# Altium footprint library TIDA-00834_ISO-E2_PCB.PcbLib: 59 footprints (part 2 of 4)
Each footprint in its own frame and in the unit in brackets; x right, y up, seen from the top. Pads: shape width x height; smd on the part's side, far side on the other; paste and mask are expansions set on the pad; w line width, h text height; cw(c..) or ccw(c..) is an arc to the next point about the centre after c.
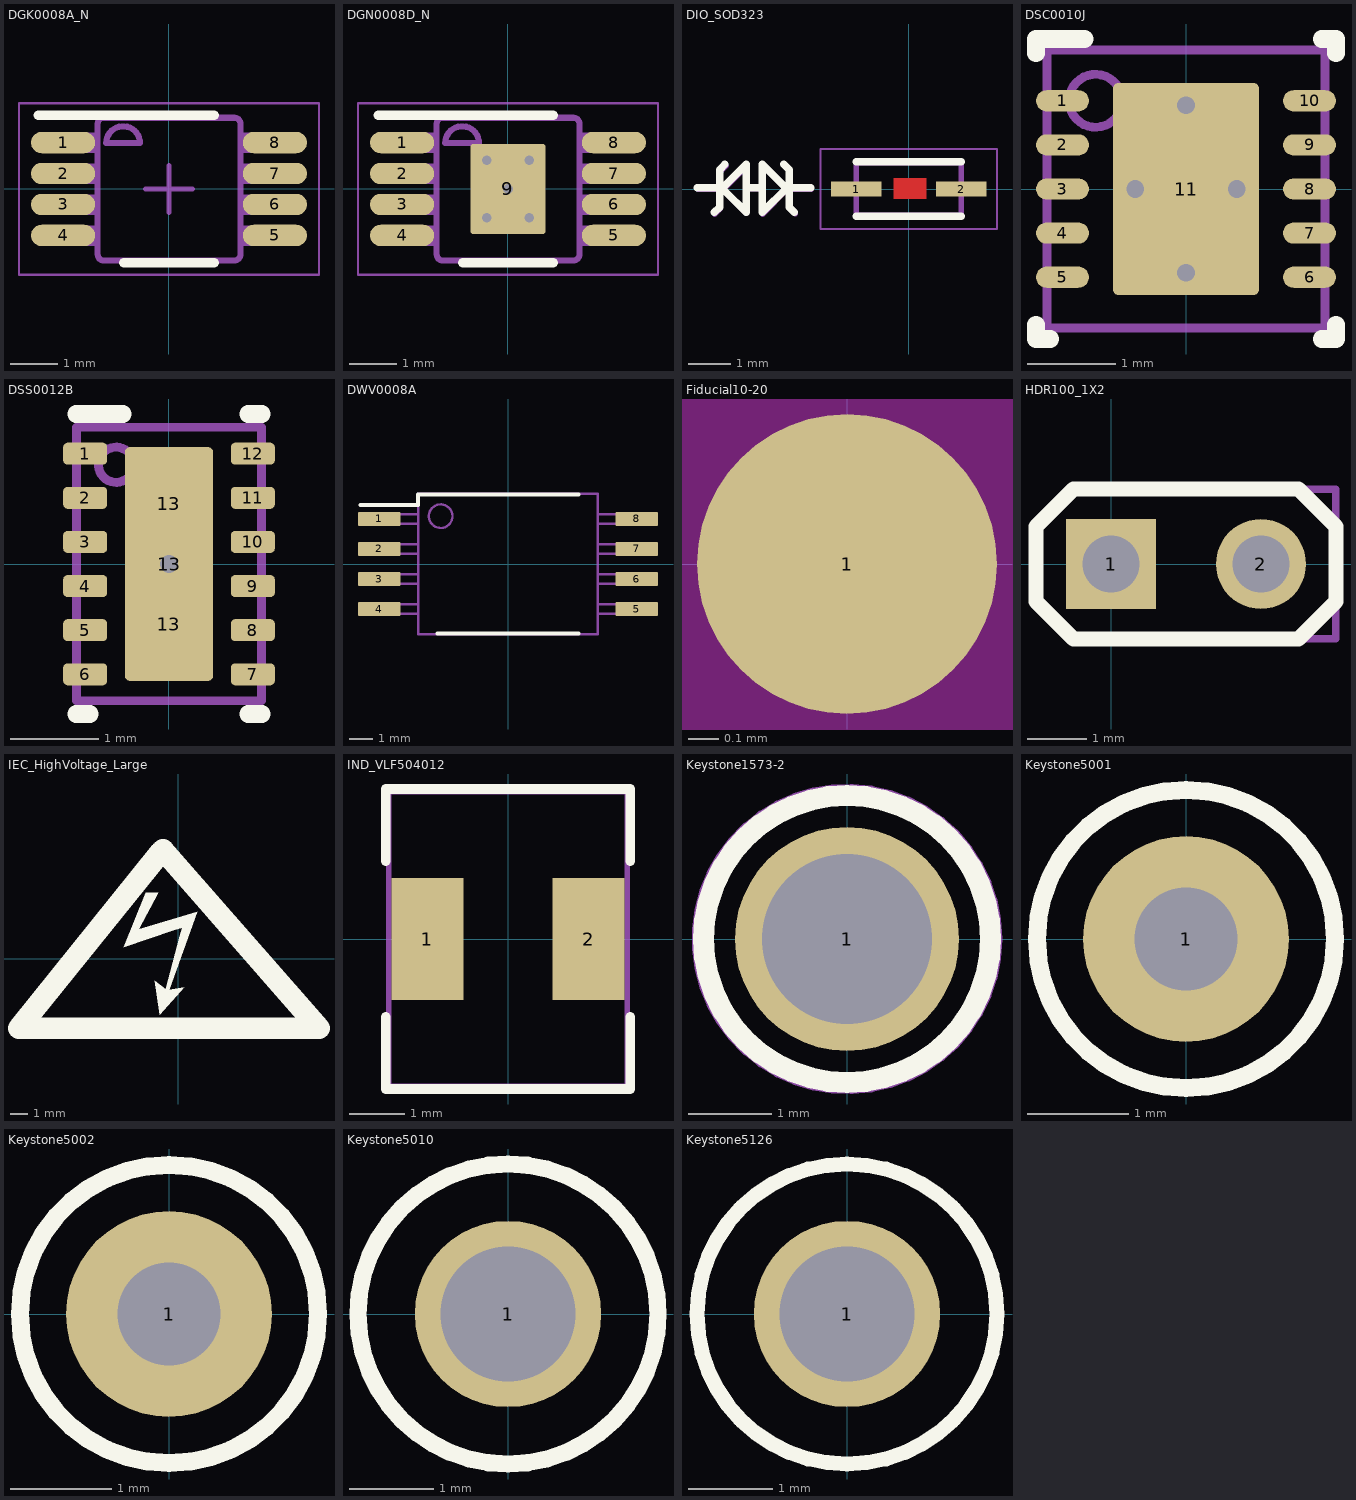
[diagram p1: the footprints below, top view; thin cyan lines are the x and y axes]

## DGK0008A_N [mm] "TSOP, 8-Leads, Body 3x3mm, Pitch 0.65mm, IPC Medium Density"
height 1.1
pads (8):
  oval 1.35x0.45 smd: 1(-2.225,0.975) 2(-2.225,0.325) 3(-2.225,-0.325) 4(-2.225,-0.975) 5(2.225,-0.975) 6(2.225,-0.325) 7(2.225,0.325) 8(2.225,0.975)
Top Overlay:
  lines w0.2: -2.75,1.55 0.95,1.55 ; -0.95,-1.55 0.95,-1.55
Mechanical 5:
  lines w0.127: -2.45,-1.131 -2.21,-1.131 -2.091,-1.131 -2.087,-1.131 -1.784,-1.131 -1.498,-1.131 -1.498,-0.826 -1.784,-0.826 -2.087,-0.826 -2.091,-0.826 -2.21,-0.826 -2.45,-0.826 -2.45,-1.131 ; -2.45,-0.48 -2.21,-0.48 -2.091,-0.48 -2.087,-0.48 -1.784,-0.48 -1.498,-0.48 -1.498,-0.175 -1.784,-0.175 -2.087,-0.175 -2.091,-0.175 -2.21,-0.175 -2.45,-0.175 -2.45,-0.48 ; -2.45,0.17 -2.21,0.17 -2.091,0.17 -2.087,0.17 -1.784,0.17 -1.498,0.17 -1.498,0.475 -1.784,0.475 -2.087,0.475 -2.091,0.475 -2.21,0.475 -2.45,0.475 -2.45,0.17 ; -2.45,0.82 -2.21,0.82 -2.091,0.82 -2.087,0.82 -1.784,0.82 -1.498,0.82 -1.498,1.125 -1.784,1.125 -2.087,1.125 -2.091,1.125 -2.21,1.125 -2.45,1.125 -2.45,0.82 ; -1.497,-1.377 ccw(c-1.37,-1.374) -1.373,-1.501 -1.371,-1.501 1.373,-1.501 1.375,-1.501 ccw(c1.373,-1.374) 1.5,-1.377 1.5,-1.374 1.5,1.369 1.5,1.372 ccw(c1.373,1.369) 1.375,1.496 1.373,1.496 -1.371,1.496 -1.373,1.496 ccw(c-1.37,1.369) -1.497,1.372 -1.498,1.369 -1.498,-1.374 -1.497,-1.377 ; -1.32,0.962 cw(c-0.964,0.962) -0.609,0.962 -1.32,0.962 ; 1.5,-1.131 1.5,-0.826 1.786,-0.826 2.089,-0.826 2.093,-0.826 2.213,-0.826 2.452,-0.826 2.452,-1.131 2.213,-1.131 2.093,-1.131 2.089,-1.131 1.786,-1.131 1.5,-1.131 ; 1.5,-0.48 1.5,-0.175 1.786,-0.175 2.089,-0.175 2.093,-0.175 2.213,-0.175 2.452,-0.175 2.452,-0.48 2.213,-0.48 2.093,-0.48 2.089,-0.48 1.786,-0.48 1.5,-0.48 ; 1.5,0.17 1.5,0.475 1.786,0.475 2.089,0.475 2.093,0.475 2.213,0.475 2.452,0.475 2.452,0.17 2.213,0.17 2.093,0.17 2.089,0.17 1.786,0.17 1.5,0.17 ; 1.5,0.82 1.5,1.125 1.786,1.125 2.089,1.125 2.093,1.125 2.213,1.125 2.452,1.125 2.452,0.82 2.213,0.82 2.093,0.82 2.089,0.82 1.786,0.82 1.5,0.82
  text ".Designator" at -0.127,0.803 h0.64
Mechanical 15:
  lines w0.05: -3.15,-1.8 3.15,-1.8 3.15,1.8 -3.15,1.8 -3.15,-1.8
  lines w0.1: -0.5,0 0.5,0 ; 0,-0.5 0,0.5
3D body "DGK0008A.stp": height 0.96, standoff 0, extent -2.451,-1.499 2.451,1.499

## DGN0008D_N [mm] "TSOP, 8-Leads, Body 3x3mm, Pitch 0.65mm, Thermal Pad 1.89x1.57mm, IPC Medium Density"
height 1.1
pads (9):
  rrect100% 1.35x0.45 smd: 1(-2.225,0.975) 2(-2.225,0.325) 3(-2.225,-0.325) 4(-2.225,-0.975) 5(2.225,-0.975) 6(2.225,-0.325) 7(2.225,0.325) 8(2.225,0.975)
  rrect6% 1.57x1.89 smd: 9(0,0)
via 0,0 diameter 0.5 hole 0.2
via 0.45,0.6 diameter 0.5 hole 0.2
via 0.45,-0.6 diameter 0.5 hole 0.2
via -0.45,-0.6 diameter 0.5 hole 0.2
via -0.45,0.6 diameter 0.5 hole 0.2
Top Overlay:
  lines w0.2: -2.725,1.55 0.95,1.55 ; -0.95,-1.55 0.95,-1.55
Mechanical 5:
  lines w0.127: -2.45,-1.131 -2.21,-1.131 -2.09,-1.131 -2.087,-1.131 -1.784,-1.131 -1.498,-1.131 -1.498,-0.826 -1.784,-0.826 -2.087,-0.826 -2.09,-0.826 -2.21,-0.826 -2.45,-0.826 -2.45,-1.131 ; -2.45,-0.48 -2.21,-0.48 -2.09,-0.48 -2.087,-0.48 -1.784,-0.48 -1.498,-0.48 -1.498,-0.175 -1.784,-0.175 -2.087,-0.175 -2.09,-0.175 -2.21,-0.175 -2.45,-0.175 -2.45,-0.48 ; -2.45,0.17 -2.21,0.17 -2.09,0.17 -2.087,0.17 -1.784,0.17 -1.498,0.17 -1.498,0.475 -1.784,0.475 -2.087,0.475 -2.09,0.475 -2.21,0.475 -2.45,0.475 -2.45,0.17 ; -2.45,0.82 -2.21,0.82 -2.09,0.82 -2.087,0.82 -1.784,0.82 -1.498,0.82 -1.498,1.125 -1.784,1.125 -2.087,1.125 -2.09,1.125 -2.21,1.125 -2.45,1.125 -2.45,0.82 ; -1.497,-1.377 ccw(c-1.37,-1.374) -1.373,-1.501 -1.371,-1.501 1.373,-1.501 1.375,-1.501 ccw(c1.373,-1.374) 1.5,-1.377 1.5,-1.374 1.5,1.369 1.5,1.372 ccw(c1.373,1.369) 1.375,1.496 1.373,1.496 -1.371,1.496 -1.373,1.496 ccw(c-1.37,1.369) -1.497,1.372 -1.498,1.369 -1.498,-1.374 -1.497,-1.377 ; -1.32,0.962 cw(c-0.964,0.962) -0.609,0.962 -1.32,0.962 ; 1.5,-1.131 1.5,-0.826 1.786,-0.826 2.089,-0.826 2.093,-0.826 2.213,-0.826 2.452,-0.826 2.452,-1.131 2.213,-1.131 2.093,-1.131 2.089,-1.131 1.786,-1.131 1.5,-1.131 ; 1.5,-0.48 1.5,-0.175 1.786,-0.175 2.089,-0.175 2.093,-0.175 2.213,-0.175 2.452,-0.175 2.452,-0.48 2.213,-0.48 2.093,-0.48 2.089,-0.48 1.786,-0.48 1.5,-0.48 ; 1.5,0.17 1.5,0.475 1.786,0.475 2.089,0.475 2.093,0.475 2.213,0.475 2.452,0.475 2.452,0.17 2.213,0.17 2.093,0.17 2.089,0.17 1.786,0.17 1.5,0.17 ; 1.5,0.82 1.5,1.125 1.786,1.125 2.089,1.125 2.093,1.125 2.213,1.125 2.452,1.125 2.452,0.82 2.213,0.82 2.093,0.82 2.089,0.82 1.786,0.82 1.5,0.82
  text ".Designator" at -0.711,-0.413 h0.64
Mechanical 15:
  lines w0.05: -3.15,-1.8 -3.15,1.8 3.15,1.8 3.15,-1.8 -3.15,-1.8
  lines w0.1: -0.5,0 0.5,0 ; 0,-0.5 0,0.5
3D body "DGN0008D.stp": height 1.1, standoff 0, extent -2.46,-1.5 2.46,1.5

## DIO_SOD323 [mm] "TVS DIODE, SOD323, SMT"
height 1.1
pads (2):
  rect 1.2x0.35 smd: 1(-1.25,0) 2(1.25,0)
Top Layer:
  region: -0.356,0.25 -0.357,-0.227 0.417,-0.227 0.415,0.25
Top Overlay:
  lines w0.178: -5.032,0.029 -4.532,0.029 ; -4.621,-0.557 -4.494,-0.43 -4.494,0.459 -4.367,0.586 ; -4.431,0.014 -3.859,0.586 -3.859,-0.557 -4.367,-0.049 ; -3.811,0.029 -3.534,0.029 ; -2.97,0.078 -3.478,0.586 -3.478,-0.557 -2.892,0.029 -2.332,0.029 ; -2.97,0.586 -2.843,0.459 -2.843,-0.43 -2.716,-0.557 ; -1.25,-0.65 1.25,-0.65 ; -1.25,0.65 1.25,0.65
Mechanical 5:
  lines w0.127: -5.015,-0.002 -4.515,-0.002 ; -4.615,-0.602 -4.475,-0.462 ; -4.475,-0.382 -4.475,0.418 -4.335,0.558 ; -4.415,-0.022 -3.855,0.538 -3.855,-0.582 -4.375,-0.062 ; -3.759,-0.001 -3.54,-0.002 ; -3.475,-0.602 -2.875,-0.002 ; -3.455,-0.582 -3.455,0.558 -2.855,-0.042 ; -2.95,0.563 -2.815,0.428 ; -2.83,-0.457 -2.695,-0.592 ; -2.815,-0.402 -2.815,0.398 ; -2.815,-0.002 -2.315,-0.002 ; -1.25,-0.625 1.25,-0.625 1.25,0.625 -1.25,0.625 -1.25,-0.625
  text ".Designator" at -0.762,-0.371 h0.64
Mechanical 15:
  lines w0.05: -2.1,-0.95 -2.1,0.95 2.1,0.95 2.1,-0.95 -2.1,-0.95
3D body: height 1.1, standoff 0, extent -1.25,-0.625 1.25,0.625

## DSC0010J [mm] "SON, 10-Leads, Body 3x3mm, Pitch 0.5mm, Thermal Pad 2.4x1.65mm, TI Recommended"
height 0.8
pads (11):
  rrect100% 0.6x0.24 smd: 1(-1.4,1) 2(-1.4,0.5) 3(-1.4,0) 4(-1.4,-0.5) 5(-1.4,-1) 6(1.4,-1) 7(1.4,-0.5) 8(1.4,0) 9(1.4,0.5) 10(1.4,1)
  rrect6% 1.65x2.4 smd paste-0.825: 11(0,0)
via 0.575,0 diameter 0.5 hole 0.2
via -0.575,0 diameter 0.5 hole 0.2
via 0,0.95 diameter 0.5 hole 0.2
via 0,-0.95 diameter 0.5 hole 0.2
Top Overlay:
  lines w0.2: -1.7,-1.54 -1.7,-1.7 -1.54,-1.7 ; -1.7,1.54 -1.7,1.7 -1.15,1.7 ; 1.54,-1.7 1.7,-1.7 1.7,-1.54 ; 1.54,1.7 1.7,1.7 1.7,1.54
Top Paste:
  rectangle: -0.75,0.1 0.75,1.16
  rectangle: -0.75,-1.16 0.75,-0.1
Mechanical 5:
  circle w0.1: c-1.025,1 r0.3
  lines w0.1: -1.575,-1.575 1.575,-1.575 1.575,1.575 -1.575,1.575 -1.575,-1.575
  text ".Designator" at -0.18,0.889 h0.64
3D body: height 0.8, standoff 0, extent -1.574,-1.574 1.574,1.574
3D body: height 0.81, standoff 0.5, extent -1.324,0.701 -0.726,1.299

## DSS0012B [mm] "SON, 12-Leads, Body 2x3mm, Pitch 0.5mm, Thermal Pad 2.65x1.0mm, TI Recommended"
height 0.8
pads (15):
  rrect40% 0.5x0.25 smd: 1(-0.95,1.25) 2(-0.95,0.75) 3(-0.95,0.25) 4(-0.95,-0.25) 5(-0.95,-0.75) 6(-0.95,-1.25) 7(0.95,-1.25) 8(0.95,-0.75) 9(0.95,-0.25) 10(0.95,0.25) 11(0.95,0.75) 12(0.95,1.25)
  rrect50% 0.949x1.168 on Top Paste: 13(0,-0.684) 13(0,0.684)
  rrect11% 1x2.65 smd paste-0.5: 13(0,0)
via 0,0 diameter 0.5 hole 0.2
Top Overlay:
  lines w0.2: -1.05,-1.7 -0.9,-1.7 ; -1.05,1.7 -0.525,1.7 ; 0.9,-1.7 1.05,-1.7 ; 0.9,1.7 1.05,1.7
Mechanical 5:
  circle w0.1: c-0.6,1.125 r0.2
  lines w0.1: -1.05,-1.55 1.05,-1.55 1.05,1.55 -1.05,1.55 -1.05,-1.55
  text ".Designator" at -0.25,0.728 h0.64
3D body "DSS0012A.stp": height 0.8, standoff 0, extent -1,-1.5 1,1.5
3D body: height 0.81, standoff 0.5, extent -0.799,0.926 -0.401,1.324

## DWV0008A [mm] "SOIC, 8-Leads, Body 5.95x7.6mm (max), Pitch 1.27mm"
height 2.8
pads (8):
  rrect17% 1.8x0.6 smd: 1(-5.45,1.905) 2(-5.45,0.635) 3(-5.45,-0.635) 4(-5.45,-1.905) 5(5.45,-1.905) 6(5.45,-0.635) 7(5.45,0.635) 8(5.45,1.905)
Top Overlay:
  lines w0.17: -6.25,2.5 -3.8,2.5 -3.8,2.95 2.975,2.95 ; -2.975,-2.95 2.975,-2.95
Mechanical 5:
  circle w0.1: c-2.85,2.025 r0.5
  lines w0.1: -3.805,-2.105 -5.8,-2.105 -5.8,-1.705 -3.805,-1.705 ; -3.805,-0.835 -5.8,-0.835 -5.8,-0.435 -3.805,-0.435 ; -3.805,0.435 -5.8,0.435 -5.8,0.835 -3.805,0.835 ; -3.805,1.705 -5.8,1.705 -5.8,2.105 -3.805,2.105 ; 3.805,-2.105 5.8,-2.105 5.8,-1.705 3.805,-1.705 ; 3.805,-0.835 5.8,-0.835 5.8,-0.435 3.805,-0.435 ; 3.805,0.435 5.8,0.435 5.8,0.835 3.805,0.835 ; 3.805,1.705 5.8,1.705 5.8,2.105 3.805,2.105 ; -3.8,-2.975 3.8,-2.975 3.8,2.975 -3.8,2.975 -3.8,-2.975
  text ".Designator" at 0.787,0.279 h0.64
3D body "DWV0008A.stp": height 2.67, standoff -0.03, extent -5.768,-2.925 5.768,2.925

## FCC_disclaimer [mm]

## Fiducial10-20 [mm]
pads (1):
  round 1 smd mask+0.5: 1(0,0)
Top Layer keep-out:
  circle w1.178: c0,0 r0.5

## HDR100_1X2 [mil]
pads (2):
  rect 60x60 hole 38: 1(0,0)
  round 60 hole 38: 2(100,0)
Top Overlay:
  lines w10: -50,-25 -50,25 -25,50 125,50 150,25 150,-25 125,-50 -25,-50 -50,-25
Mechanical 5:
  lines w5: -50,-25 -25,-50 150,-50 150,50 -25,50 -50,25 -50,-25
  text ".Designator" at 84,12 h25

## IEC_HighVoltage_Large [mm]
Top Overlay:
  region: -1.884,3.845 -1.156,3.845 -2.282,1.711 1.117,2.736 -0.532,-1.803 0.359,-1.641 -1.063,-3.267 -1.368,-1.286 -0.733,-1.768 0.099,1.318 0.232,1.813 -0.254,1.651 -3.167,0.68
  lines w1.27: -1.016,6.223 -9.271,-4.039 8.204,-4.039 -0.889,6.35

## IND_VLF504012 [mm] "TDK"
height 1.2
pads (2):
  rect 1.3x2.2 smd: 1(-1.45,0) 2(1.45,0)
Top Overlay:
  lines w0.178: -2.2,-1.4 -2.2,-2.7 2.2,-2.7 2.2,-1.4 ; -2.2,1.4 -2.2,2.7 2.2,2.7 2.2,1.4
Mechanical 5:
  lines w0.1: -2.15,-2.65 2.15,-2.65 2.15,2.65 -2.15,2.65 -2.15,-2.65
  text ".Designator" at 0.279,-0.483 h0.64
3D body: height 1.2, standoff 0, extent -2.149,-2.649 2.149,2.649

## Keystone1573-2 [mm] "Double Turret"
height 4.7
pads (1):
  round 2.7 hole 2.05: 1(0,0)
Top Overlay:
  circle w0.254: c0,0 r1.727
Mechanical 5:
  circle w0.127: c0,0 r1.805
  text ".Designator" at -1.194,-0.305 h0.64
3D body "Keystone1573-2.stp": height 4.72, standoff -2.06, extent -1.18,-1.178 1.171,1.178

## Keystone5001 [mil] "For Keystone 500x miniature loop terminals"
height 181.1
pads (1):
  round 80 hole 40: 1(0,0)
Top Overlay:
  circle w7: c0,0 r58
Mechanical 5:
  circle w5: c0,0 r58.31
  text ".Designator" at -45,-10 h25
3D body "Keystone_5001.stp": height 181.97, standoff -118.11, extent -49,-49 49.04,49.24

## Keystone5002 [mil] "For Keystone 500x miniature loop terminals"
height 181.1
pads (1):
  round 80 hole 40: 1(0,0)
Top Overlay:
  circle w7: c0,0 r58
Mechanical 5:
  circle w5: c0,0 r58.31
  text ".Designator" at -45,-10 h25
3D body "Keystone_5002.stp": height 181.97, standoff -118.11, extent -49,-49 49.04,49.23

## Keystone5010 [mil] "Keystone Multipurpose loops"
height 320
pads (1):
  round 87 hole 63: 1(0,0)
Top Overlay:
  circle w7.99: c0,0 r70
Mechanical 5:
  circle w5: c0,0 r69.46
  text ".Designator" at 9.87,-47 h25
3D body "Keystone_5010.stp": height 318.9, standoff -125.98, extent -63,-63 62.74,62.49

## Keystone5126 [mil] "Keystone Multipurpose loops"
height 320
pads (1):
  round 87 hole 63: 1(0,0)
Top Overlay:
  circle w7: c0,0 r70
Mechanical 5:
  circle w5: c0,0 r69.46
  text ".Designator" at 10.37,-46 h25
3D body "Keystone_5126.stp": height 318.9, standoff -125.98, extent -62.62,-63.37 62.86,62.36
